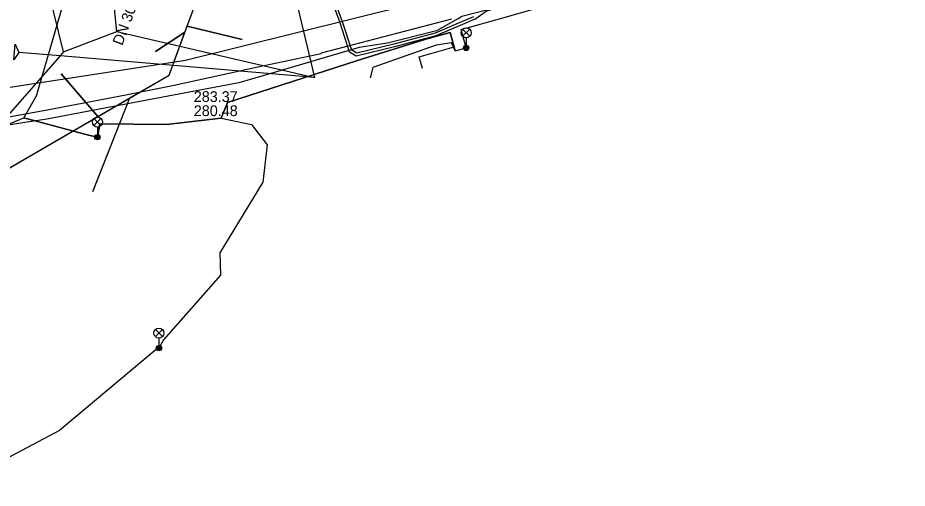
# Model space of a CAD drawing. Extents: x -599854 to -599675, y -1160809 to -1160543.
# Drawn here: x -599745.4 to -599679.2, y -1160644.7 to -1160609.7 of the extents above; entities that cross this region are included whole.
import ezdxf

# ---------------------------------------------------------------- set-up
doc = ezdxf.new("R2010")
doc.units = 0
for name, color, linetype in [('BKOM-ODVODNENI_trasa sítě', 7, 'Continuous'), ('BVK-VODOVOD_trasa zrušené sítě', 7, 'Continuous'), ('DESTOVA-NEPROVOZOVANA_popisy', 7, 'Continuous'), ('DESTOVA_trasa neprovozované sítě', 7, 'Continuous'), ('DPMB_kyneta', 7, 'Continuous'), ('DPMB_trolejové vedení-nosné lano', 7, 'Continuous'), ('DSP-JEDNOTNA-BVK_trasa sítě', 7, 'Continuous'), ('EON-NN_kabel', 7, 'Continuous'), ('EON-VN_kabel', 7, 'Continuous'), ('EON-VN_kabel zrušené sítě', 7, 'Continuous'), ('TSB_kabel VO', 7, 'Continuous'), ('TSB_lampy VO', 7, 'Continuous')]:
    doc.layers.add(name, color=color, linetype=linetype)

msp = doc.modelspace()

# ---------------------------------------------------------------- linework, layer by layer
at = {"layer": 'BKOM-ODVODNENI_trasa sítě'}
for points in [[(-599734.15, -1160614), (-599732.8, -1160610.35), (-599728.85, -1160599.72)], [(-599735.14, -1160612.215), (-599732.963, -1160610.803)], [(-599728.717, -1160611.374), (-599732.796, -1160610.353)], [(-599760.76, -1160629.44), (-599734.15, -1160614)], [(-599742.148, -1160613.915), (-599739.456, -1160617.079)], [(-599739.799, -1160622.595), (-599737.061, -1160615.689)]]:
    msp.add_lwpolyline(points, dxfattribs=at)
at = {"layer": 'BVK-VODOVOD_trasa zrušené sítě'}
msp.add_lwpolyline([(-599679.2237, -1160599.5579), (-599732.933, -1160612.912), (-599785.657, -1160621.012)], dxfattribs=at)
at = {"layer": 'DESTOVA-NEPROVOZOVANA_popisy'}
msp.add_line((-599732.309, -1160617.044), (-599732.309, -1160617.044), dxfattribs=at)
at = {"layer": 'DESTOVA_trasa neprovozované sítě'}
for p, q in [((-599735.16, -1160612.23), (-599732.963, -1160610.803)), ((-599728.71, -1160611.34), (-599732.796, -1160610.353)), ((-599742.18, -1160613.89), (-599739.456, -1160617.079)), ((-599739.82, -1160622.65), (-599737.061, -1160615.689))]:
    msp.add_line(p, q, dxfattribs=at)
for points in [[(-599734.15, -1160614), (-599732.963, -1160610.803), (-599732.796, -1160610.353), (-599729.021, -1160600.181), (-599728.85, -1160599.72)], [(-599760.76, -1160629.44), (-599739.456, -1160617.079), (-599737.061, -1160615.689), (-599734.15, -1160614)]]:
    msp.add_lwpolyline(points, dxfattribs=at)
at = {"layer": 'DPMB_kyneta'}
for points in [[(-599715.53, -1160612.64), (-599712.94, -1160611.89)], [(-599712.85, -1160612.2), (-599712.94, -1160611.89)], [(-599715.28, -1160613.51), (-599715.53, -1160612.64)]]:
    msp.add_lwpolyline(points, dxfattribs=at)
at = {"layer": 'DPMB_trolejové vedení-nosné lano'}
for points in [[(-599738.1, -1160610.04), (-599738.52, -1160605.74)], [(-599742.37, -1160610.76), (-599743.34, -1160606.79)], [(-599724.83, -1160607.82), (-599723.33, -1160614.17)], [(-599738.03, -1160610.76), (-599738.1, -1160610.04)], [(-599742, -1160612.27), (-599742.37, -1160610.76)], [(-599742, -1160612.27), (-599738.03, -1160610.76)], [(-599738.03, -1160610.76), (-599723.33, -1160614.17)], [(-599745.708, -1160612.854), (-599745.61, -1160611.702), (-599745.328, -1160612.306), (-599745.708, -1160612.854)], [(-599742.26, -1160612.57), (-599747.76, -1160618.8)], [(-599742.26, -1160612.57), (-599745.328, -1160612.306)], [(-599742, -1160612.27), (-599742.26, -1160612.57)], [(-599723.33, -1160614.17), (-599742.26, -1160612.57)]]:
    msp.add_lwpolyline(points, dxfattribs=at)
at = {"layer": 'DSP-JEDNOTNA-BVK_trasa sítě'}
for p, q in [((-599732.796, -1160610.353), (-599729.021, -1160600.181)), ((-599732.963, -1160610.803), (-599735.16, -1160612.23)), ((-599734.15, -1160614), (-599732.963, -1160610.803)), ((-599732.963, -1160610.803), (-599732.796, -1160610.353)), ((-599732.796, -1160610.353), (-599728.71, -1160611.34)), ((-599739.456, -1160617.079), (-599742.18, -1160613.89)), ((-599737.061, -1160615.689), (-599734.15, -1160614)), ((-599739.82, -1160622.65), (-599737.061, -1160615.689)), ((-599739.456, -1160617.079), (-599737.061, -1160615.689)), ((-599760.76, -1160629.44), (-599739.456, -1160617.079))]:
    msp.add_line(p, q, dxfattribs=at)
at = {"layer": 'EON-NN_kabel'}
for points in [[(-599711.392, -1160609.849), (-599710.551, -1160609.231), (-599710.082, -1160609.086), (-599695.021, -1160605.277), (-599679.855, -1160601.386), (-599679.2237, -1160601.2192)], [(-599711.392, -1160609.849), (-599712.312, -1160610.222), (-599714.287, -1160611.065), (-599717.365, -1160611.897), (-599720.216, -1160612.577), (-599720.713, -1160612.287), (-599721.425, -1160610.103), (-599722.936, -1160605.988)], [(-599711.488, -1160609.671), (-599712.388, -1160610.038), (-599714.353, -1160610.875), (-599717.415, -1160611.703), (-599720.184, -1160612.363), (-599720.547, -1160612.153), (-599721.235, -1160610.037), (-599722.744, -1160605.932)]]:
    msp.add_lwpolyline(points, dxfattribs=at)
at = {"layer": 'EON-VN_kabel'}
for points in [[(-599712.66, -1160609.8), (-599712.36, -1160609.62), (-599702.21, -1160606.98), (-599690.58, -1160604.02), (-599683.76, -1160602.34), (-599679.81, -1160601.27), (-599679.2237, -1160601.1246)], [(-599712.66, -1160609.8), (-599714.25, -1160610.71), (-599717.89, -1160611.61), (-599720, -1160611.94), (-599726.57, -1160613.87), (-599728.96, -1160614.58), (-599736.45, -1160615.99), (-599743.23, -1160617.28), (-599748.93, -1160618.14)]]:
    msp.add_lwpolyline(points, dxfattribs=at)
at = {"layer": 'EON-VN_kabel zrušené sítě'}
msp.add_lwpolyline([(-599771.83, -1160621.47), (-599767.08, -1160620.85), (-599761.41, -1160619.81), (-599756.57, -1160618.89), (-599746.77, -1160617.22), (-599743.21, -1160616.58), (-599737.23, -1160615.44), (-599733.76, -1160614.74), (-599727.53, -1160613.39), (-599722.82, -1160612.38), (-599722.81, -1160612.35), (-599713.101, -1160609.819)], dxfattribs=at)
at = {"layer": 'TSB_kabel VO'}
for points in [[(-599712.85, -1160612.2), (-599713.231, -1160610.818), (-599715.05, -1160611.32), (-599720.13, -1160612.91), (-599729.8, -1160616.03), (-599730.26, -1160617.21), (-599734.33, -1160617.68), (-599739.29, -1160617.63), (-599739.48, -1160618.61), (-599740.14, -1160618.47), (-599744.95, -1160617.17), (-599744.01, -1160615.53), (-599741.64, -1160607.33), (-599740.03, -1160599.74), (-599742.84, -1160597.94), (-599743.59, -1160597.21), (-599749.46, -1160587.62), (-599756.62, -1160578.69), (-599758.16, -1160577.35), (-599762.32, -1160572.73), (-599766.71, -1160568.47)], [(-599712.85, -1160612.2), (-599712.04, -1160611.97), (-599712.419, -1160610.595), (-599709.21, -1160609.71), (-599701.69, -1160607.54), (-599695.84, -1160605.63), (-599685.36, -1160602.84), (-599684.11, -1160601.08), (-599683.03, -1160601.17)], [(-599712.85, -1160612.2), (-599713.231, -1160610.818), (-599715.05, -1160611.32), (-599720.13, -1160612.91), (-599729.8, -1160616.03), (-599730.26, -1160617.21), (-599728.02, -1160617.68), (-599726.84, -1160619.19), (-599727.17, -1160621.95), (-599730.36, -1160627.21), (-599730.33, -1160628.86), (-599734.57, -1160633.68), (-599734.9, -1160634.3), (-599735.11, -1160634.4), (-599742.3, -1160640.42), (-599750.4, -1160644.71)], [(-599745.97, -1160617.59), (-599744.95, -1160617.17), (-599740.14, -1160618.47), (-599739.48, -1160618.61), (-599739.29, -1160617.63), (-599734.33, -1160617.68), (-599730.26, -1160617.21), (-599729.8, -1160616.03), (-599720.13, -1160612.91), (-599715.05, -1160611.32), (-599713.231, -1160610.818), (-599712.85, -1160612.2)], [(-599712.85, -1160612.2), (-599713.121, -1160611.592), (-599714.261, -1160611.766), (-599718.981, -1160613.43), (-599719.184, -1160614.203)]]:
    msp.add_lwpolyline(points, dxfattribs=at)
at = {"layer": 'TSB_lampy VO'}
for p, q in [((-599712.305, -1160611.11), (-599711.775, -1160610.58)), ((-599712.305, -1160610.58), (-599711.775, -1160611.11)), ((-599712.305, -1160611.11), (-599711.775, -1160610.58)), ((-599712.305, -1160610.58), (-599711.775, -1160611.11)), ((-599712.04, -1160611.22), (-599712.04, -1160611.97)), ((-599712.04, -1160611.22), (-599712.04, -1160611.97)), ((-599739.745, -1160617.75), (-599739.215, -1160617.22)), ((-599739.745, -1160617.22), (-599739.215, -1160617.75)), ((-599739.745, -1160617.75), (-599739.215, -1160617.22)), ((-599739.745, -1160617.22), (-599739.215, -1160617.75)), ((-599739.48, -1160617.86), (-599739.48, -1160618.61)), ((-599739.48, -1160617.86), (-599739.48, -1160618.61)), ((-599735.165, -1160633.44), (-599734.635, -1160632.91)), ((-599735.165, -1160632.91), (-599734.635, -1160633.44)), ((-599735.165, -1160633.44), (-599734.635, -1160632.91)), ((-599735.165, -1160632.91), (-599734.635, -1160633.44)), ((-599734.9, -1160633.55), (-599734.9, -1160634.3)), ((-599734.9, -1160633.55), (-599734.9, -1160634.3))]:
    msp.add_line(p, q, dxfattribs=at)
for centre, radius in [((-599712.04, -1160610.845), 0.375), ((-599712.04, -1160610.845), 0.375), ((-599712.04, -1160611.97), 0.2), ((-599712.04, -1160611.97), 0.2), ((-599712.04, -1160611.97), 0.1445), ((-599712.04, -1160611.97), 0.1445), ((-599712.04, -1160611.97), 0.0876), ((-599712.04, -1160611.97), 0.0876), ((-599739.48, -1160617.485), 0.375), ((-599739.48, -1160617.485), 0.375), ((-599739.48, -1160618.61), 0.2), ((-599739.48, -1160618.61), 0.2), ((-599739.48, -1160618.61), 0.1445), ((-599739.48, -1160618.61), 0.1445), ((-599739.48, -1160618.61), 0.0876), ((-599739.48, -1160618.61), 0.0876), ((-599734.9, -1160633.175), 0.375), ((-599734.9, -1160633.175), 0.375), ((-599734.9, -1160634.3), 0.2), ((-599734.9, -1160634.3), 0.2), ((-599734.9, -1160634.3), 0.1445), ((-599734.9, -1160634.3), 0.1445), ((-599734.9, -1160634.3), 0.0876), ((-599734.9, -1160634.3), 0.0876)]:
    msp.add_circle(centre, radius, dxfattribs=at)

# ---------------------------------------------------------------- texts
at = {"layer": 'DESTOVA-NEPROVOZOVANA_popisy'}
msp.add_text('DN 300 KAM', height=0.8, rotation=69.637669, dxfattribs=at).set_placement((-599737.63, -1160611.842))
for s, p in [('283.37', (-599732.309, -1160615.994)), ('280.48', (-599732.309, -1160617.044))]:
    msp.add_text(s, height=0.8, dxfattribs=at).set_placement(p)

doc.saveas('drawing.dxf')
